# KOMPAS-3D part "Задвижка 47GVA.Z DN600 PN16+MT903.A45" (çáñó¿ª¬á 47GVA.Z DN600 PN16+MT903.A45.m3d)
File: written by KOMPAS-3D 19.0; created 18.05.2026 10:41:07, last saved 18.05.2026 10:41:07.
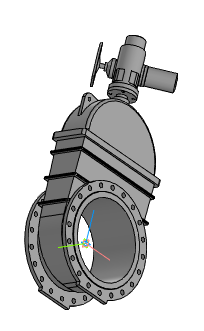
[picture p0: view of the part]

Document properties: Автор: Энергия; Полное имя файла: ..\Задвижка 47GVA.Z DN350_DN1200+MT903.A\Задвижка 47GVA.Z DN600 PN16+MT903.A45.a3d

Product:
- Part/product: Задвижка 47GVA.Z DN600 PN16+MT903.A45
    Масса: 1622.12
  - Body: Электропривод МТ903.А45 без блока управления
      Масса: 175.721
  - Body: Задвижка 47GVA.Z DN600 PN16 без исполнит. мех.
      Масса: 1446.4

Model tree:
1. Операция без истории:1
2. Операция без истории:2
